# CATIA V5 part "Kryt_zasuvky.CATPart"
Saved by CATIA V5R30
Part number: Kryt_zasuvky
Definition: 2025_05_12_09_08_15_0864
Nomenclature: 2025_05_12_09_08_15_0864
Source: Unknown
Description: PART--DESC
Bounding box of the stored display mesh (mm): x -99 to 14, y -31 to 58.983, z 0 to 88.3
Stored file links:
  E:\Bakalarka\Model\Forma_v7\Kryt_zasuvky.CATPart
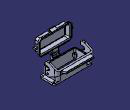
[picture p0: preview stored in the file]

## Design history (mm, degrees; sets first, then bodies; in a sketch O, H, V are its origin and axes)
Body1 "E2716_16B_NAUO1#E2716_16B;Importiert1" (main body)
  Solid1: solid without history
